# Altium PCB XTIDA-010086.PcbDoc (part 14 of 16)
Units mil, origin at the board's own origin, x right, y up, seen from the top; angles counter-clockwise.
Board outline 14763.78 x 8267.72 mil, 6 copper layers (Top Layer, GND Layer, Signal Layer 1, Signal Layer 2, Power Layer, Bottom Layer), stack 62 mil thick; 1933 components, 1002 nets, 4886 pads, 6482 vias.
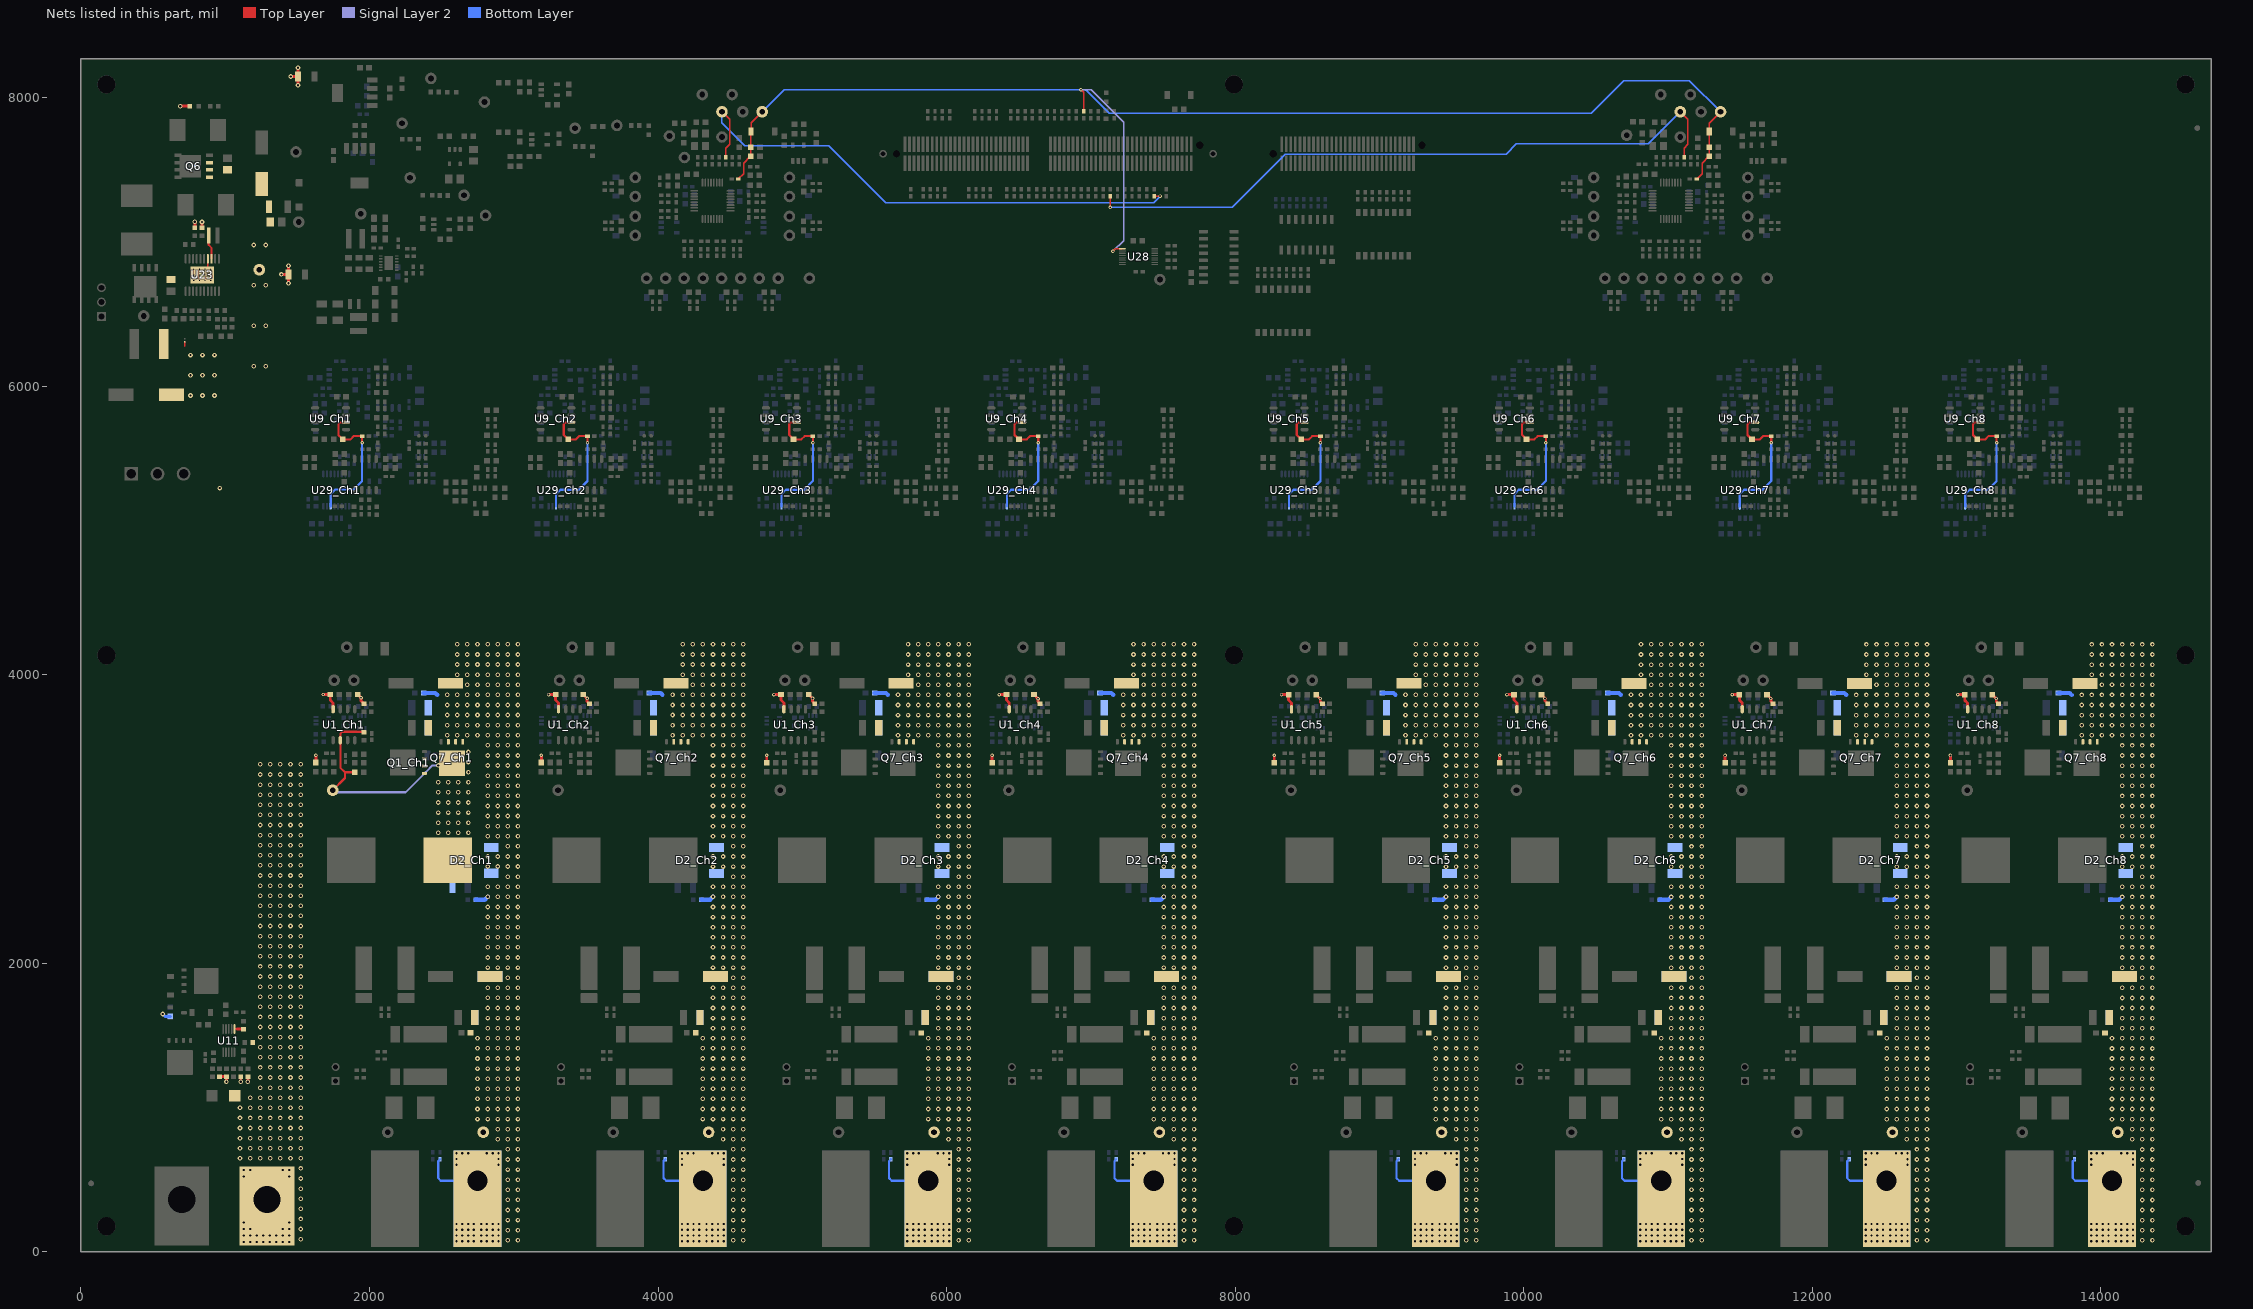
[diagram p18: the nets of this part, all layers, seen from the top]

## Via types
v1: diameter 32, hole 16, Top Layer to Bottom Layer, tented both sides, 4685 vias
v2: diameter 24, hole 12, Top Layer to Bottom Layer, tented both sides, 1013 vias
v3: diameter 32, hole 16, Top Layer to Bottom Layer, 728 vias
v4: diameter 19.68, hole 7.87, Top Layer to Bottom Layer, 40 vias
v5: diameter 214.57, hole 140, Top Layer to Bottom Layer, 16 vias

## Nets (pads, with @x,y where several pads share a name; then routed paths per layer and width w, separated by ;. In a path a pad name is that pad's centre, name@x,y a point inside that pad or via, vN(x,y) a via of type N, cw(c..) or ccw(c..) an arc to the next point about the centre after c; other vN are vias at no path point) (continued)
PGND: C3_Ch1.2 C3_Ch2.2 C3_Ch3.2 C3_Ch4.2 C3_Ch5.2 C3_Ch6.2 C3_Ch7.2 C3_Ch8.2 C4_Ch1.2 C4_Ch2.2 C4_Ch3.2 C4_Ch4.2 C4_Ch5.2 C4_Ch6.2 C4_Ch7.2 C4_Ch8.2 C5_Ch1.2 C5_Ch2.2 C5_Ch3.2 C5_Ch4.2 C5_Ch5.2 C5_Ch6.2 C5_Ch7.2 C5_Ch8.2 C6_Ch1.2 C6_Ch2.2 C6_Ch3.2 C6_Ch4.2 C6_Ch5.2 C6_Ch6.2 C6_Ch7.2 C6_Ch8.2 C7_Ch1.2 C7_Ch2.2 C7_Ch3.2 C7_Ch4.2 C7_Ch5.2 C7_Ch6.2 C7_Ch7.2 C7_Ch8.2 C8_Ch1.1 C8_Ch2.1 C8_Ch3.1 C8_Ch4.1 C8_Ch5.1 C8_Ch6.1 C8_Ch7.1 C8_Ch8.1 C9_Ch1.2 C9_Ch2.2 C9_Ch3.2 C9_Ch4.2 C9_Ch5.2 C9_Ch6.2 C9_Ch7.2 C9_Ch8.2 C10_Ch1.2 C10_Ch2.2 C10_Ch3.2 C10_Ch4.2 C10_Ch5.2 C10_Ch6.2 C10_Ch7.2 C10_Ch8.2 C11_Ch1.2 C11_Ch2.2 C11_Ch3.2 C11_Ch4.2 C11_Ch5.2 C11_Ch6.2 C11_Ch7.2 C11_Ch8.2 C12_Ch1.2 C12_Ch2.2 C12_Ch3.2 C12_Ch4.2 C12_Ch5.2 C12_Ch6.2 C12_Ch7.2 C12_Ch8.2 C13_Ch1.2 C13_Ch2.2 C13_Ch3.2 C13_Ch4.2 C13_Ch5.2 C13_Ch6.2 C13_Ch7.2 C13_Ch8.2 C15_Ch1.1 C15_Ch2.1 C15_Ch3.1 C15_Ch4.1 C15_Ch5.1 C15_Ch6.1 C15_Ch7.1 C15_Ch8.1 C56.1 C57.1 C58.2 C59.1 C109.2 C110.2 C111.2 C113.2 C114.2 C118.2 C119.2 C121.2 C137.2 D2_Ch1.1 D2_Ch1.3 D2_Ch2.1 D2_Ch2.3 D2_Ch3.1 D2_Ch3.3 D2_Ch4.1 D2_Ch4.3 D2_Ch5.1 D2_Ch5.3 D2_Ch6.1 D2_Ch6.3 D2_Ch7.1 D2_Ch7.3 D2_Ch8.1 D2_Ch8.3 D8.2 D11.1 J3_Ch1.1 J3_Ch2.1 J3_Ch3.1 J3_Ch4.1 J3_Ch5.1 J3_Ch6.1 J3_Ch7.1 J3_Ch8.1 NT1.2 Q6.1 Q6.2 Q6.3 Q7_Ch1.1 Q7_Ch1.2 Q7_Ch1.3 Q7_Ch2.1 Q7_Ch2.2 Q7_Ch2.3 Q7_Ch3.1 Q7_Ch3.2 Q7_Ch3.3 Q7_Ch4.1 Q7_Ch4.2 Q7_Ch4.3 Q7_Ch5.1 Q7_Ch5.2 Q7_Ch5.3 Q7_Ch6.1 Q7_Ch6.2 Q7_Ch6.3 Q7_Ch7.1 Q7_Ch7.2 Q7_Ch7.3 Q7_Ch8.1 Q7_Ch8.2 Q7_Ch8.3 R1_Ch1.2 R1_Ch2.2 R1_Ch3.2 R1_Ch4.2 R1_Ch5.2 R1_Ch6.2 R1_Ch7.2 R1_Ch8.2 R5_Ch1.1 R5_Ch2.1 R5_Ch3.1 R5_Ch4.1 R5_Ch5.1 R5_Ch6.1 R5_Ch7.1 R5_Ch8.1 R20_Ch1.1 R20_Ch2.1 R20_Ch3.1 R20_Ch4.1 R20_Ch5.1 R20_Ch6.1 R20_Ch7.1 R20_Ch8.1 R24_Ch1.1 R24_Ch2.1 R24_Ch3.1 R24_Ch4.1 R24_Ch5.1 R24_Ch6.1 R24_Ch7.1 R24_Ch8.1 R81.1 R88.1 R89.1 R152.1 R153.2 R211.1 T2.1 TP6_Ch1.1 TP6_Ch2.1 TP6_Ch3.1 TP6_Ch4.1 TP6_Ch5.1 TP6_Ch6.1 TP6_Ch7.1 TP6_Ch8.1 TP34.1 U1_Ch1.4 U1_Ch2.4 U1_Ch3.4 U1_Ch4.4 U1_Ch5.4 U1_Ch6.4 U1_Ch7.4 U1_Ch8.4 U11.6 U23.13 U23.14 U23.21 | length 8236.9
  Top Layer w10: U11.6@1064.7,1544.48 1083.48,1544.48
  Top Layer w12: 721,6277.7 NT1.2@721,6306.7 ; U23.21@841.5,6769.7 879.89,6808.09 U23.14@879.89,6881.91 ; R211.1@885.49,7043.7 885.49,6978.21 905.48,6958.22 U23.13@905.48,6881.91
  Top Layer w20: v1(689,7939.7) D11.1@754.5,7939.7 ; C118.2@789.5,7098.26 790,7098.76 v1(790,7137.7) ; C119.2@839.01,7097.76 C119.2@839.5,7098.26 v1(839.5,7137.2) ; R89.1@960.54,1214.2 C57.1@1009.04,1214.2 v1(1009.04,1178) ; 1083.48,1544.48 1126.85,1544.48 C56.1@1127.33,1544 C56.1@1127,1543.67 ; v1(1107.83,1177.8) R88.1@1107.83,1214 ; v1(1157.33,1177.8) C59.1@1157.33,1214 ; v1(1390,6773.7) R153.2@1439.11,6773.7 ; v1(1439.11,6712.81) R153.2@1439.11,6773.7 ; v1(1439.11,6834.59) R153.2@1439.11,6773.7 ; v1(1455.7,8145) R152.1@1504.81,8145 ; v1(1504.81,8084.11) R152.1@1504.81,8145 ; v1(1504.81,8205.89) R152.1@1504.81,8145 ; R24_Ch1.1@1629.36,3390.59 v2(1629.36,3440.86) ; v2(1679.31,3862.31) R5_Ch1.1@1728.62,3862.31 1728.62,3823.61 1748.37,3803.86 U1_Ch1.4@1748.37,3760.35 ; R1_Ch1.2@1919.61,3862.31 v2(1941.81,3840.11) 1941.81,3819.34 C8_Ch1.1@1962.33,3798.82 ; R24_Ch2.1@3191.36,3390.51 v2(3191.36,3440.79) ; v2(3241.31,3862.24) R5_Ch2.1@3290.62,3862.24 3290.62,3823.53 3310.37,3803.78 U1_Ch2.4@3310.37,3760.27 ; R1_Ch2.2@3481.61,3862.24 v2(3508.81,3835.04) 3508.81,3814.26 C8_Ch2.1@3524.33,3798.74 ; R24_Ch3.1@4753.36,3390.43 v2(4753.36,3440.71) ; v2(4803.31,3862.16) R5_Ch3.1@4852.62,3862.16 4852.62,3823.45 4872.37,3803.7 U1_Ch3.4@4872.37,3760.19 ; R1_Ch3.2@5043.61,3862.16 v2(5070.81,3834.96) 5070.81,3814.18 C8_Ch3.1@5086.33,3798.66 ; R24_Ch4.1@6315.36,3390.35 v2(6315.36,3440.63) ; v2(6365.31,3862.08) R5_Ch4.1@6414.62,3862.08 6414.62,3823.37 6434.37,3803.62 U1_Ch4.4@6434.37,3760.12 ; R1_Ch4.2@6605.61,3862.08 v2(6634.15,3833.53) 6634.15,3812.76 C8_Ch4.1@6648.33,3798.58 ; R24_Ch5.1@8271.06,3390.27 v2(8271.06,3440.55) ; v2(8321.01,3862) R5_Ch5.1@8370.32,3862 8370.32,3823.3 8390.07,3803.54 U1_Ch5.4@8390.07,3760.04 ; R1_Ch5.2@8561.31,3862 8588.51,3834.8 v2(8589.8,3834.8) 8589.8,3812.74 C8_Ch5.1@8604.03,3798.5 ; R24_Ch6.1@9833.06,3390.19 v2(9833.06,3440.47) ; v2(9883.01,3861.92) R5_Ch6.1@9932.32,3861.92 9932.32,3823.22 9952.07,3803.46 U1_Ch6.4@9952.07,3759.96 ; R1_Ch6.2@10123.31,3861.92 10146.7,3838.53 v2(10146.7,3834.72) 10146.7,3817.75 C8_Ch6.1@10166.03,3798.42 ; R24_Ch7.1@11395.06,3390.12 v2(11395.06,3440.39) ; v2(11445.01,3861.84) R5_Ch7.1@11494.32,3861.84 11494.32,3823.14 11514.07,3803.38 U1_Ch7.4@11514.07,3759.88 ; R1_Ch7.2@11685.31,3861.84 v2(11712.51,3834.64) 11712.51,3813.87 C8_Ch7.1@11728.03,3798.34 ; R24_Ch8.1@12957.06,3390.04 v2(12957.06,3440.31) ; v2(13007.01,3861.76) R5_Ch8.1@13056.32,3861.76 13056.32,3823.06 13076.07,3803.31 U1_Ch8.4@13076.07,3759.8 ; R1_Ch8.2@13247.31,3861.76 v2(13274.51,3834.56) 13274.51,3813.79 C8_Ch8.1@13290.03,3798.27
  Bottom Layer w15: R20_Ch1.1@2489,641.38 2476.5,628.88 2476.5,511.24 2494.74,493 v5(2749,493) ; R20_Ch2.1@4051,641.3 4038.5,628.8 4038.5,511.16 4056.74,492.92 v5(4311,492.92) ; R20_Ch3.1@5613,641.22 5600.5,628.72 5600.5,511.08 5618.74,492.84 v5(5873,492.84) ; R20_Ch4.1@7175,641.14 7162.5,628.64 7162.5,511 7180.74,492.76 v5(7435,492.76) ; R20_Ch5.1@9130.7,641.06 9118.2,628.56 9118.2,510.93 9136.44,492.69 v5(9390.7,492.69) ; R20_Ch6.1@10692.7,640.98 10680.2,628.48 10680.2,510.85 10698.44,492.61 v5(10952.7,492.61) ; R20_Ch7.1@12254.7,640.91 12242.2,628.41 12242.2,510.77 12260.44,492.53 v5(12514.7,492.53) ; R20_Ch8.1@13816.7,640.83 13804.2,628.33 13804.2,510.69 13822.44,492.45 v5(14076.7,492.45)
  Bottom Layer w20: v1(568,1648) 584.03,1631.97 R81.1@620.09,1631.97
  Bottom Layer w30: C7_Ch1.2@2377.5,3873 2456,3873 2469,3860 ; C15_Ch1.1@2737.56,2440 2799,2440 v1(2819,2460) ; C7_Ch2.2@3939.5,3872.92 4018,3872.92 4031,3859.92 ; C15_Ch2.1@4299.56,2439.92 4361,2439.92 v1(4381,2459.92) ; C7_Ch3.2@5501.5,3872.84 5580,3872.84 5593,3859.84 ; C15_Ch3.1@5861.56,2439.84 5923,2439.84 v1(5943,2459.84) ; C7_Ch4.2@7063.5,3872.76 7142,3872.76 7155,3859.76 ; C15_Ch4.1@7423.56,2439.76 7485,2439.76 v1(7505,2459.76) ; C7_Ch5.2@9019.2,3872.69 9097.7,3872.69 9110.7,3859.69 ; C15_Ch5.1@9379.26,2439.69 9440.7,2439.69 v1(9460.7,2459.69) ; C7_Ch6.2@10581.2,3872.61 10659.7,3872.61 10672.7,3859.61 ; C15_Ch6.1@10941.26,2439.61 11002.7,2439.61 v1(11022.7,2459.61) ; C7_Ch7.2@12143.2,3872.53 12221.7,3872.53 12234.7,3859.53 ; C15_Ch7.1@12503.26,2439.53 12564.7,2439.53 v1(12584.7,2459.53) ; C7_Ch8.2@13705.2,3872.45 13783.7,3872.45 13796.7,3859.45 ; C15_Ch8.1@14065.26,2439.45 14126.7,2439.45 v1(14146.7,2459.45)
  other v1: 11162.7,79.61 11232.7,79.61 12724.7,79.53 12794.7,79.53 14286.7,79.45 14356.7,79.45 2959,80 3029,80 4521,79.92 4591,79.92 6083,79.84 6153,79.84 7645,79.76 7715,79.76 9600.7,79.69 9670.7,79.69 1523,88 11162.7,149.61 11232.7,149.61 12724.7,149.53 12794.7,149.53 14286.7,149.45 14356.7,149.45 2959,150 3029,150 4521,149.92 4591,149.92 6083,149.84 6153,149.84 7645,149.76 7715,149.76 9600.7,149.69 9670.7,149.69 1523,158 11162.7,219.61 11232.7,219.61 12724.7,219.53 12794.7,219.53 14286.7,219.45 14356.7,219.45 2959,220 3029,220 4521,219.92 4591,219.92 6083,219.84 6153,219.84 7645,219.76 7715,219.76 9600.7,219.69 9670.7,219.69 1523,228 11162.7,289.61 11232.7,289.61 12724.7,289.53 12794.7,289.53 14286.7,289.45 14356.7,289.45 2959,290 3029,290 4521,289.92 4591,289.92 6083,289.84 6153,289.84 7645,289.76 7715,289.76 9600.7,289.69 9670.7,289.69 1523,298 11162.7,359.61 11232.7,359.61 12724.7,359.53 12794.7,359.53 14286.7,359.45 14356.7,359.45 2959,360 3029,360 4521,359.92 4591,359.92 6083,359.84 6153,359.84 7645,359.76 7715,359.76 9600.7,359.69 9670.7,359.69 1523,368 11162.7,429.61 11232.7,429.61 12724.7,429.53 12794.7,429.53 14286.7,429.45 14356.7,429.45 2959,430 3029,430 4521,429.92 4591,429.92 6083,429.84 6153,429.84 7645,429.76 7715,429.76 9600.7,429.69 9670.7,429.69 1523,438 11162.7,499.61 11232.7,499.61 12724.7,499.53 12794.7,499.53 14286.7,499.45 14356.7,499.45 2959,500 3029,500 4521,499.92 4591,499.92 6083,499.84 6153,499.84 7645,499.76 7715,499.76 9600.7,499.69 9670.7,499.69 1523,508 11162.7,569.61 11232.7,569.61 12724.7,569.53 12794.7,569.53 14286.7,569.45 14356.7,569.45 2959,570 3029,570 4521,569.92 4591,569.92 6083,569.84 6153,569.84 7645,569.76 7715,569.76 9600.7,569.69 9670.7,569.69 1523,578 11162.7,639.61 11232.7,639.61 12724.7,639.53 12794.7,639.53 14286.7,639.45 14356.7,639.45 2959,640 3029,640 4521,639.92 4591,639.92 6083,639.84 6153,639.84 7645,639.76 7715,639.76 9600.7,639.69 9670.7,639.69 1103,648 1173,648 1243,648 1313,648 1383,648 1453,648 1523,648 11162.7,709.61 11232.7,709.61 12724.7,709.53 12794.7,709.53 14286.7,709.45 14356.7,709.45 2959,710 3029,710 4521,709.92 4591,709.92 6083,709.84 6153,709.84 7645,709.76 7715,709.76 9600.7,709.69 9670.7,709.69 1103,718 1173,718 1243,718 1313,718 1383,718 1453,718 1523,718 11092.7,779.61 11162.7,779.61 11232.7,779.61 12654.7,779.53 12724.7,779.53 12794.7,779.53 14216.7,779.45 14286.7,779.45 14356.7,779.45 2889,780 2959,780 3029,780 4451,779.92 4521,779.92 4591,779.92 6013,779.84 6083,779.84 6153,779.84 7575,779.76 7645,779.76 7715,779.76 9530.7,779.69 9600.7,779.69 9670.7,779.69 1103,788 1173,788 1243,788 1313,788 1383,788 1453,788 1523,788 11092.7,849.61 11162.7,849.61 11232.7,849.61 12654.7,849.53 12724.7,849.53 12794.7,849.53 14216.7,849.45 14286.7,849.45 14356.7,849.45 2889,850 2959,850 3029,850 4451,849.92 4521,849.92 4591,849.92 6013,849.84 6083,849.84 6153,849.84 7575,849.76 7645,849.76 7715,849.76 9530.7,849.69 9600.7,849.69 9670.7,849.69 1103,858 1173,858 1243,858 1313,858 1383,858 1453,858 1523,858 10952.7,919.61 11022.7,919.61 11092.7,919.61 11162.7,919.61 11232.7,919.61 12514.7,919.53 12584.7,919.53 12654.7,919.53 12724.7,919.53 12794.7,919.53 14076.7,919.45 14146.7,919.45 14216.7,919.45 14286.7,919.45 14356.7,919.45 2749,920 2819,920 2889,920 2959,920 3029,920 4311,919.92 4381,919.92 4451,919.92 4521,919.92 4591,919.92 5873,919.84 5943,919.84 6013,919.84 6083,919.84 6153,919.84 7435,919.76 7505,919.76 7575,919.76 7645,919.76 7715,919.76 9390.7,919.69 9460.7,919.69 9530.7,919.69 9600.7,919.69 9670.7,919.69 1103,928 1173,928 1243,928 1313,928 1383,928 1453,928 1523,928 10952.7,989.61 11022.7,989.61 11092.7,989.61 11162.7,989.61 11232.7,989.61 12514.7,989.53 12584.7,989.53 12654.7,989.53 12724.7,989.53 12794.7,989.53 14076.7,989.45 14146.7,989.45 14216.7,989.45 14286.7,989.45 14356.7,989.45 2749,990 2819,990 2889,990 2959,990 3029,990 4311,989.92 4381,989.92 4451,989.92 4521,989.92 4591,989.92 5873,989.84 5943,989.84 6013,989.84 6083,989.84 6153,989.84 7435,989.76 7505,989.76 7575,989.76 7645,989.76 7715,989.76 9390.7,989.69 9460.7,989.69 9530.7,989.69 9600.7,989.69 9670.7,989.69 1103,998 1173,998 1243,998 1313,998 1383,998 1453,998 1523,998 10952.7,1059.61 11022.7,1059.61 11092.7,1059.61 11162.7,1059.61 11232.7,1059.61 12514.7,1059.53 12584.7,1059.53 12654.7,1059.53 12724.7,1059.53 12794.7,1059.53 14076.7,1059.45 14146.7,1059.45 14216.7,1059.45 14286.7,1059.45 14356.7,1059.45 2749,1060 2819,1060 2889,1060 2959,1060 3029,1060 4311,1059.92 4381,1059.92 4451,1059.92 4521,1059.92 4591,1059.92 5873,1059.84 5943,1059.84 6013,1059.84 6083,1059.84 6153,1059.84 7435,1059.76 7505,1059.76 7575,1059.76 7645,1059.76 7715,1059.76 9390.7,1059.69 9460.7,1059.69 9530.7,1059.69 9600.7,1059.69 9670.7,1059.69 1173,1068 1243,1068 1313,1068 1383,1068 1453,1068 1523,1068 10952.7,1129.61 11022.7,1129.61 11092.7,1129.61 11162.7,1129.61 11232.7,1129.61 12514.7,1129.53 12584.7,1129.53 12654.7,1129.53 12724.7,1129.53 12794.7,1129.53 14076.7,1129.45 14146.7,1129.45 14216.7,1129.45 14286.7,1129.45 14356.7,1129.45 2749,1130 2819,1130 2889,1130 2959,1130 3029,1130 4311,1129.92 4381,1129.92 4451,1129.92 4521,1129.92 4591,1129.92 5873,1129.84 5943,1129.84 6013,1129.84 6083,1129.84 6153,1129.84 7435,1129.76 7505,1129.76 7575,1129.76 7645,1129.76 7715,1129.76 9390.7,1129.69 9460.7,1129.69 9530.7,1129.69 9600.7,1129.69 9670.7,1129.69 1243,1138 1313,1138 1383,1138 1453,1138 1523,1138 10952.7,1199.61 11022.7,1199.61 11092.7,1199.61 11162.7,1199.61 11232.7,1199.61 12514.7,1199.53 12584.7,1199.53 12654.7,1199.53 12724.7,1199.53 12794.7,1199.53 14076.7,1199.45 14146.7,1199.45 14216.7,1199.45 14286.7,1199.45 14356.7,1199.45 2749,1200 2819,1200 2889,1200 2959,1200 3029,1200 4311,1199.92 4381,1199.92 4451,1199.92 4521,1199.92 4591,1199.92 5873,1199.84 5943,1199.84 6013,1199.84 6083,1199.84 6153,1199.84 7435,1199.76 7505,1199.76 7575,1199.76 7645,1199.76 7715,1199.76 9390.7,1199.69 9460.7,1199.69 9530.7,1199.69 9600.7,1199.69 9670.7,1199.69 1243,1208 1313,1208 1383,1208 1453,1208 1523,1208 10952.7,1269.61 11022.7,1269.61 11092.7,1269.61 11162.7,1269.61 11232.7,1269.61 12514.7,1269.53 12584.7,1269.53 12654.7,1269.53 12724.7,1269.53 12794.7,1269.53 14076.7,1269.45 14146.7,1269.45 14216.7,1269.45 14286.7,1269.45 14356.7,1269.45 2749,1270 2819,1270 2889,1270 2959,1270 3029,1270 4311,1269.92 4381,1269.92 4451,1269.92 4521,1269.92 4591,1269.92 5873,1269.84 5943,1269.84 6013,1269.84 6083,1269.84 6153,1269.84 7435,1269.76 7505,1269.76 7575,1269.76 7645,1269.76 7715,1269.76 9390.7,1269.69 9460.7,1269.69 9530.7,1269.69 9600.7,1269.69 9670.7,1269.69 1243,1278 1313,1278 1383,1278 1453,1278 1523,1278 10952.7,1339.61 11022.7,1339.61 11092.7,1339.61 11162.7,1339.61 11232.7,1339.61 12514.7,1339.53 12584.7,1339.53 12654.7,1339.53 12724.7,1339.53 12794.7,1339.53 14076.7,1339.45 14146.7,1339.45 14216.7,1339.45 14286.7,1339.45 14356.7,1339.45 2749,1340 2819,1340 2889,1340 2959,1340 3029,1340 4311,1339.92 4381,1339.92 4451,1339.92 4521,1339.92 4591,1339.92 5873,1339.84 5943,1339.84 6013,1339.84 6083,1339.84 6153,1339.84 7435,1339.76 7505,1339.76 7575,1339.76 7645,1339.76 7715,1339.76 9390.7,1339.69 9460.7,1339.69 9530.7,1339.69 9600.7,1339.69 9670.7,1339.69 1243,1348 1313,1348 1383,1348 1453,1348 1523,1348 10952.7,1409.61 11022.7,1409.61 11092.7,1409.61 11162.7,1409.61 11232.7,1409.61 12514.7,1409.53 12584.7,1409.53 12654.7,1409.53 12724.7,1409.53 12794.7,1409.53 14076.7,1409.45 14146.7,1409.45 14216.7,1409.45 14286.7,1409.45 14356.7,1409.45 2749,1410 2819,1410 2889,1410 2959,1410 3029,1410 4311,1409.92 4381,1409.92 4451,1409.92 4521,1409.92 4591,1409.92 5873,1409.84 5943,1409.84 6013,1409.84 6083,1409.84 6153,1409.84 7435,1409.76 7505,1409.76 7575,1409.76 7645,1409.76 7715,1409.76 9390.7,1409.69 9460.7,1409.69 9530.7,1409.69 9600.7,1409.69 9670.7,1409.69 1243,1418 1313,1418 1383,1418 1453,1418 1523,1418 10952.7,1479.61 11022.7,1479.61 11092.7,1479.61 11162.7,1479.61 11232.7,1479.61 12514.7,1479.53 12584.7,1479.53 12654.7,1479.53 12724.7,1479.53 12794.7,1479.53 14076.7,1479.45 14146.7,1479.45 14216.7,1479.45 14286.7,1479.45 14356.7,1479.45 2749,1480 2819,1480 2889,1480 2959,1480 3029,1480 4311,1479.92 4381,1479.92 4451,1479.92 4521,1479.92 4591,1479.92 5873,1479.84 5943,1479.84 6013,1479.84 6083,1479.84 6153,1479.84 7435,1479.76 7505,1479.76 7575,1479.76 7645,1479.76 7715,1479.76 9390.7,1479.69 9460.7,1479.69 9530.7,1479.69 9600.7,1479.69 9670.7,1479.69 1243,1488 1313,1488 1383,1488 1453,1488 1523,1488 11022.7,1549.61 11092.7,1549.61 11162.7,1549.61 11232.7,1549.61 12584.7,1549.53 12654.7,1549.53 12724.7,1549.53 12794.7,1549.53 14146.7,1549.45 14216.7,1549.45 14286.7,1549.45 14356.7,1549.45 2819,1550 2889,1550 2959,1550 3029,1550 4381,1549.92 4451,1549.92 4521,1549.92 4591,1549.92 5943,1549.84 6013,1549.84 6083,1549.84 6153,1549.84 7505,1549.76 7575,1549.76 7645,1549.76 7715,1549.76 9460.7,1549.69 9530.7,1549.69 9600.7,1549.69 9670.7,1549.69 1243,1558 1313,1558 1383,1558 1453,1558 1523,1558 11022.7,1619.61 11092.7,1619.61 11162.7,1619.61 11232.7,1619.61 12584.7,1619.53 12654.7,1619.53 12724.7,1619.53 12794.7,1619.53 14146.7,1619.45 14216.7,1619.45 14286.7,1619.45 14356.7,1619.45 2819,1620 2889,1620 2959,1620 3029,1620 4381,1619.92 4451,1619.92 4521,1619.92 4591,1619.92 5943,1619.84 6013,1619.84 6083,1619.84 6153,1619.84 7505,1619.76 7575,1619.76 7645,1619.76 7715,1619.76 9460.7,1619.69 9530.7,1619.69 9600.7,1619.69 9670.7,1619.69 1243,1628 1313,1628 1383,1628 1453,1628 1523,1628 11022.7,1689.61 11092.7,1689.61 11162.7,1689.61 11232.7,1689.61 12584.7,1689.53 12654.7,1689.53 12724.7,1689.53 12794.7,1689.53 14146.7,1689.45 14216.7,1689.45 14286.7,1689.45 14356.7,1689.45 2819,1690 2889,1690 2959,1690 3029,1690 4381,1689.92 4451,1689.92 4521,1689.92 4591,1689.92 5943,1689.84 6013,1689.84 6083,1689.84 6153,1689.84 7505,1689.76 7575,1689.76 7645,1689.76 7715,1689.76 9460.7,1689.69 9530.7,1689.69 9600.7,1689.69 9670.7,1689.69 1243,1698 1313,1698 1383,1698 1453,1698 1523,1698 11022.7,1759.61 11092.7,1759.61 11162.7,1759.61 11232.7,1759.61 12584.7,1759.53 12654.7,1759.53 12724.7,1759.53 12794.7,1759.53 14146.7,1759.45 14216.7,1759.45 14286.7,1759.45 14356.7,1759.45 2819,1760 2889,1760 2959,1760 3029,1760 4381,1759.92 4451,1759.92 4521,1759.92 4591,1759.92 5943,1759.84 6013,1759.84 6083,1759.84 6153,1759.84 7505,1759.76 7575,1759.76 7645,1759.76 7715,1759.76 9460.7,1759.69 9530.7,1759.69 9600.7,1759.69 9670.7,1759.69 1243,1768 1313,1768 1383,1768 1453,1768 1523,1768 11022.7,1829.61 11092.7,1829.61 11162.7,1829.61 11232.7,1829.61 12584.7,1829.53 12654.7,1829.53 12724.7,1829.53 12794.7,1829.53 14146.7,1829.45 14216.7,1829.45 14286.7,1829.45 14356.7,1829.45 2819,1830 2889,1830 2959,1830 3029,1830 4381,1829.92 4451,1829.92 4521,1829.92 4591,1829.92 5943,1829.84 6013,1829.84 6083,1829.84 6153,1829.84 7505,1829.76 7575,1829.76 7645,1829.76 7715,1829.76 9460.7,1829.69 9530.7,1829.69 9600.7,1829.69 9670.7,1829.69 1243,1838 1313,1838 1383,1838 1453,1838 1523,1838 11162.7,1899.61 11232.7,1899.61 12724.7,1899.53 12794.7,1899.53 14286.7,1899.45 14356.7,1899.45 2959,1900 3029,1900 4521,1899.92 4591,1899.92 6083,1899.84 6153,1899.84 7645,1899.76 7715,1899.76 9600.7,1899.69 9670.7,1899.69 1243,1908 1313,1908 1383,1908 1453,1908 1523,1908 11022.7,1969.61 11092.7,1969.61 11162.7,1969.61 11232.7,1969.61 12584.7,1969.53 12654.7,1969.53 12724.7,1969.53 12794.7,1969.53 14146.7,1969.45 14216.7,1969.45 14286.7,1969.45 14356.7,1969.45 2819,1970 2889,1970 2959,1970 3029,1970 4381,1969.92 4451,1969.92 4521,1969.92 4591,1969.92 5943,1969.84 6013,1969.84 6083,1969.84 6153,1969.84 7505,1969.76 7575,1969.76 7645,1969.76 7715,1969.76 9460.7,1969.69 9530.7,1969.69 9600.7,1969.69 9670.7,1969.69 1243,1978 1313,1978 1383,1978 1453,1978 1523,1978 11022.7,2039.61 11092.7,2039.61 11162.7,2039.61 11232.7,2039.61 12584.7,2039.53 12654.7,2039.53 12724.7,2039.53 12794.7,2039.53 14146.7,2039.45 14216.7,2039.45 14286.7,2039.45 14356.7,2039.45 2819,2040 2889,2040 2959,2040 3029,2040 4381,2039.92 4451,2039.92 4521,2039.92 4591,2039.92 5943,2039.84 6013,2039.84 6083,2039.84 6153,2039.84 7505,2039.76 7575,2039.76 7645,2039.76 7715,2039.76 9460.7,2039.69 9530.7,2039.69 9600.7,2039.69 9670.7,2039.69 1243,2048 1313,2048 1383,2048 1453,2048 1523,2048 11022.7,2109.61 11092.7,2109.61 11162.7,2109.61 11232.7,2109.61 12584.7,2109.53 12654.7,2109.53 12724.7,2109.53 12794.7,2109.53 14146.7,2109.45 14216.7,2109.45 14286.7,2109.45 14356.7,2109.45 2819,2110 2889,2110 2959,2110 3029,2110 4381,2109.92 4451,2109.92 4521,2109.92 4591,2109.92 5943,2109.84 6013,2109.84 6083,2109.84 6153,2109.84 7505,2109.76 7575,2109.76 7645,2109.76 7715,2109.76 9460.7,2109.69 9530.7,2109.69 9600.7,2109.69 9670.7,2109.69 1243,2118 1313,2118 1383,2118 1453,2118 1523,2118 11022.7,2179.61 11092.7,2179.61 11162.7,2179.61 11232.7,2179.61 12584.7,2179.53 12654.7,2179.53 12724.7,2179.53 12794.7,2179.53 14146.7,2179.45 14216.7,2179.45 14286.7,2179.45 14356.7,2179.45 2819,2180 2889,2180 2959,2180 3029,2180 4381,2179.92 4451,2179.92 4521,2179.92 4591,2179.92 5943,2179.84 6013,2179.84 6083,2179.84 6153,2179.84 7505,2179.76 7575,2179.76 7645,2179.76 7715,2179.76 9460.7,2179.69 9530.7,2179.69 9600.7,2179.69 9670.7,2179.69 1243,2188 1313,2188 1383,2188 1453,2188 1523,2188 11022.7,2249.61 11092.7,2249.61 11162.7,2249.61 11232.7,2249.61 12584.7,2249.53 12654.7,2249.53 12724.7,2249.53 12794.7,2249.53 14146.7,2249.45 14216.7,2249.45 14286.7,2249.45 14356.7,2249.45 2819,2250 2889,2250 2959,2250 3029,2250 4381,2249.92 4451,2249.92 4521,2249.92 4591,2249.92 5943,2249.84 6013,2249.84 6083,2249.84 6153,2249.84 7505,2249.76 7575,2249.76 7645,2249.76 7715,2249.76 9460.7,2249.69 9530.7,2249.69 9600.7,2249.69 9670.7,2249.69 1243,2258 1313,2258 1383,2258 1453,2258 1523,2258 11022.7,2319.61 11092.7,2319.61 11162.7,2319.61 11232.7,2319.61 12584.7,2319.53 12654.7,2319.53 12724.7,2319.53 12794.7,2319.53 14146.7,2319.45 14216.7,2319.45 14286.7,2319.45 14356.7,2319.45 2819,2320 2889,2320 2959,2320 3029,2320 4381,2319.92 4451,2319.92 4521,2319.92 4591,2319.92 5943,2319.84 6013,2319.84 6083,2319.84 6153,2319.84 7505,2319.76 7575,2319.76 7645,2319.76 7715,2319.76 9460.7,2319.69 9530.7,2319.69 9600.7,2319.69 9670.7,2319.69 1243,2328 1313,2328 1383,2328 1453,2328 1523,2328 11022.7,2389.61 11092.7,2389.61 11162.7,2389.61 11232.7,2389.61 12584.7,2389.53 12654.7,2389.53 12724.7,2389.53 12794.7,2389.53 14146.7,2389.45 14216.7,2389.45 14286.7,2389.45 14356.7,2389.45 2819,2390 2889,2390 2959,2390 3029,2390 4381,2389.92 4451,2389.92 4521,2389.92 4591,2389.92 5943,2389.84 6013,2389.84 6083,2389.84 6153,2389.84 7505,2389.76 7575,2389.76 7645,2389.76 7715,2389.76 9460.7,2389.69 9530.7,2389.69 9600.7,2389.69 9670.7,2389.69 1243,2398 1313,2398 1383,2398 1453,2398 1523,2398 11092.7,2459.61 11162.7,2459.61 11232.7,2459.61 12654.7,2459.53 12724.7,2459.53 12794.7,2459.53 14216.7,2459.45 14286.7,2459.45 14356.7,2459.45 2889,2460 2959,2460 3029,2460 4451,2459.92 4521,2459.92 4591,2459.92 6013,2459.84 6083,2459.84 6153,2459.84 7575,2459.76 7645,2459.76 7715,2459.76 9530.7,2459.69 9600.7,2459.69 9670.7,2459.69 1243,2468 1313,2468 1383,2468 1453,2468 1523,2468 11022.7,2529.61 11092.7,2529.61 11162.7,2529.61 11232.7,2529.61 12584.7,2529.53 12654.7,2529.53 12724.7,2529.53 12794.7,2529.53 14146.7,2529.45 14216.7,2529.45 14286.7,2529.45 14356.7,2529.45 2819,2530 2889,2530 2959,2530 3029,2530 4381,2529.92 4451,2529.92 4521,2529.92 4591,2529.92 5943,2529.84 6013,2529.84 6083,2529.84 6153,2529.84 7505,2529.76 7575,2529.76 7645,2529.76 7715,2529.76 9460.7,2529.69 9530.7,2529.69 9600.7,2529.69 9670.7,2529.69 1243,2538 1313,2538 1383,2538 1453,2538 1523,2538 11162.7,2599.61 11232.7,2599.61 12724.7,2599.53 12794.7,2599.53 14286.7,2599.45 14356.7,2599.45 2959,2600 3029,2600 4521,2599.92 4591,2599.92 6083,2599.84 6153,2599.84 7645,2599.76 7715,2599.76 9600.7,2599.69 9670.7,2599.69 1243,2608 1313,2608 1383,2608 1453,2608 1523,2608 11022.7,2669.61 11092.7,2669.61 11162.7,2669.61 11232.7,2669.61 12584.7,2669.53 12654.7,2669.53 12724.7,2669.53 12794.7,2669.53 14146.7,2669.45 14216.7,2669.45 14286.7,2669.45 14356.7,2669.45 2819,2670 2889,2670 2959,2670 3029,2670 4381,2669.92 4451,2669.92 4521,2669.92 4591,2669.92 5943,2669.84 6013,2669.84 6083,2669.84 6153,2669.84 7505,2669.76 7575,2669.76 7645,2669.76 7715,2669.76 9460.7,2669.69 9530.7,2669.69 9600.7,2669.69 9670.7,2669.69 1243,2678 1313,2678 1383,2678 1453,2678 1523,2678 11022.7,2739.61 11092.7,2739.61 11162.7,2739.61 11232.7,2739.61 12584.7,2739.53 12654.7,2739.53 12724.7,2739.53 12794.7,2739.53 14146.7,2739.45 14216.7,2739.45 14286.7,2739.45 14356.7,2739.45 2819,2740 2889,2740 2959,2740 3029,2740 4381,2739.92 4451,2739.92 4521,2739.92 4591,2739.92 5943,2739.84 6013,2739.84 6083,2739.84 6153,2739.84 7505,2739.76 7575,2739.76 7645,2739.76 7715,2739.76 9460.7,2739.69 9530.7,2739.69 9600.7,2739.69 9670.7,2739.69 1243,2748 1313,2748 1383,2748 1453,2748 1523,2748 11162.7,2809.61 11232.7,2809.61 12724.7,2809.53 12794.7,2809.53 14286.7,2809.45 14356.7,2809.45 2959,2810 3029,2810 4521,2809.92 4591,2809.92 6083,2809.84 6153,2809.84 7645,2809.76 7715,2809.76 9600.7,2809.69 9670.7,2809.69 1243,2818 1313,2818 1383,2818 1453,2818 1523,2818 11022.7,2879.61 11092.7,2879.61 11162.7,2879.61 11232.7,2879.61 12584.7,2879.53 12654.7,2879.53 12724.7,2879.53 12794.7,2879.53 14146.7,2879.45 14216.7,2879.45 14286.7,2879.45 14356.7,2879.45 2819,2880 2889,2880 2959,2880 3029,2880 4381,2879.92 4451,2879.92 4521,2879.92 4591,2879.92 5943,2879.84 6013,2879.84 6083,2879.84 6153,2879.84 7505,2879.76 7575,2879.76 7645,2879.76 7715,2879.76 9460.7,2879.69 9530.7,2879.69 9600.7,2879.69 9670.7,2879.69 1243,2888 1313,2888 1383,2888 1453,2888 1523,2888 11022.7,2949.61 11092.7,2949.61 11162.7,2949.61 11232.7,2949.61 12584.7,2949.53 12654.7,2949.53 12724.7,2949.53 12794.7,2949.53 14146.7,2949.45 14216.7,2949.45 14286.7,2949.45 14356.7,2949.45 2819,2950 2889,2950 2959,2950 3029,2950 4381,2949.92 4451,2949.92 4521,2949.92 4591,2949.92 5943,2949.84 6013,2949.84 6083,2949.84 6153,2949.84 7505,2949.76 7575,2949.76 7645,2949.76 7715,2949.76 9460.7,2949.69 9530.7,2949.69 9600.7,2949.69 9670.7,2949.69 1243,2958 1313,2958 1383,2958 1453,2958 1523,2958 11022.7,3019.61 11092.7,3019.61 11162.7,3019.61 11232.7,3019.61 12584.7,3019.53 12654.7,3019.53 12724.7,3019.53 12794.7,3019.53 14146.7,3019.45 14216.7,3019.45 14286.7,3019.45 14356.7,3019.45 2819,3020 2889,3020 2959,3020 3029,3020 4381,3019.92 4451,3019.92 4521,3019.92 4591,3019.92 5943,3019.84 6013,3019.84 6083,3019.84 6153,3019.84 7505,3019.76 7575,3019.76 7645,3019.76 7715,3019.76 9460.7,3019.69 9530.7,3019.69 9600.7,3019.69 9670.7,3019.69 1243,3028 1313,3028 1383,3028 1453,3028 1523,3028 11022.7,3089.61 11092.7,3089.61 11162.7,3089.61 11232.7,3089.61 12584.7,3089.53 12654.7,3089.53 12724.7,3089.53 12794.7,3089.53 14146.7,3089.45 14216.7,3089.45 14286.7,3089.45 14356.7,3089.45 2819,3090 2889,3090 2959,3090 3029,3090 4381,3089.92 4451,3089.92 4521,3089.92 4591,3089.92 5943,3089.84 6013,3089.84 6083,3089.84 6153,3089.84 7505,3089.76 7575,3089.76 7645,3089.76 7715,3089.76 9460.7,3089.69 9530.7,3089.69 9600.7,3089.69 9670.7,3089.69 1243,3098 1313,3098 1383,3098 1453,3098 1523,3098 11022.7,3159.61 11092.7,3159.61 11162.7,3159.61 11232.7,3159.61 12584.7,3159.53 12654.7,3159.53 12724.7,3159.53 12794.7,3159.53 14146.7,3159.45 14216.7,3159.45 14286.7,3159.45 14356.7,3159.45 2819,3160 2889,3160 2959,3160 3029,3160 4381,3159.92 4451,3159.92 4521,3159.92 4591,3159.92 5943,3159.84 6013,3159.84 6083,3159.84 6153,3159.84 7505,3159.76 7575,3159.76 7645,3159.76 7715,3159.76 9460.7,3159.69 9530.7,3159.69 9600.7,3159.69 9670.7,3159.69 1243,3168 1313,3168 1383,3168 1453,3168 1523,3168 11022.7,3229.61 11092.7,3229.61 11162.7,3229.61 11232.7,3229.61 12584.7,3229.53 12654.7,3229.53 12724.7,3229.53 12794.7,3229.53 14146.7,3229.45 14216.7,3229.45 14286.7,3229.45 14356.7,3229.45 2819,3230 2889,3230 2959,3230 3029,3230 4381,3229.92 4451,3229.92 4521,3229.92 4591,3229.92 5943,3229.84 6013,3229.84 6083,3229.84 6153,3229.84 7505,3229.76 7575,3229.76 7645,3229.76 7715,3229.76 9460.7,3229.69 9530.7,3229.69 9600.7,3229.69 9670.7,3229.69 1243,3238 1313,3238 1383,3238 1453,3238 1523,3238 11022.7,3299.61 11092.7,3299.61 11162.7,3299.61 11232.7,3299.61 12584.7,3299.53 12654.7,3299.53 12724.7,3299.53 12794.7,3299.53 14146.7,3299.45 14216.7,3299.45 14286.7,3299.45 14356.7,3299.45 2819,3300 2889,3300 2959,3300 3029,3300 4381,3299.92 4451,3299.92 4521,3299.92 4591,3299.92 5943,3299.84 6013,3299.84 6083,3299.84 6153,3299.84 7505,3299.76 7575,3299.76 7645,3299.76 7715,3299.76 9460.7,3299.69 9530.7,3299.69 9600.7,3299.69 9670.7,3299.69 1243,3308 1313,3308 1383,3308 1453,3308 1523,3308 11022.7,3369.61 11092.7,3369.61 11162.7,3369.61 11232.7,3369.61 12584.7,3369.53 12654.7,3369.53 12724.7,3369.53 12794.7,3369.53 14146.7,3369.45 14216.7,3369.45 14286.7,3369.45 14356.7,3369.45 2819,3370 2889,3370 2959,3370 3029,3370 4381,3369.92 4451,3369.92 4521,3369.92 4591,3369.92 5943,3369.84 6013,3369.84 6083,3369.84 6153,3369.84 7505,3369.76 7575,3369.76 7645,3369.76 7715,3369.76 9460.7,3369.69 9530.7,3369.69 9600.7,3369.69 9670.7,3369.69 1243,3378 1313,3378 1383,3378 1453,3378 1523,3378 11022.7,3439.61 11092.7,3439.61 11162.7,3439.61 11232.7,3439.61 12584.7,3439.53 12654.7,3439.53 12724.7,3439.53 12794.7,3439.53 14146.7,3439.45 14216.7,3439.45 14286.7,3439.45 14356.7,3439.45 2819,3440 2889,3440 2959,3440 3029,3440 4381,3439.92 4451,3439.92 4521,3439.92 4591,3439.92 5943,3439.84 6013,3439.84 6083,3439.84 6153,3439.84 7505,3439.76 7575,3439.76 7645,3439.76 7715,3439.76 9460.7,3439.69 9530.7,3439.69 9600.7,3439.69 9670.7,3439.69 11022.7,3509.61 11092.7,3509.61 11162.7,3509.61 11232.7,3509.61 12584.7,3509.53 12654.7,3509.53 12724.7,3509.53 12794.7,3509.53 14146.7,3509.45 14216.7,3509.45 14286.7,3509.45 14356.7,3509.45 2819,3510 2889,3510 2959,3510 3029,3510 4381,3509.92 4451,3509.92 4521,3509.92 4591,3509.92 5943,3509.84 6013,3509.84 6083,3509.84 6153,3509.84 7505,3509.76 7575,3509.76 7645,3509.76 7715,3509.76 9460.7,3509.69 9530.7,3509.69 9600.7,3509.69 9670.7,3509.69 10742.7,3579.61 10812.7,3579.61 10882.7,3579.61 10952.7,3579.61 11022.7,3579.61 11092.7,3579.61 11162.7,3579.61 11232.7,3579.61 12304.7,3579.53 12374.7,3579.53 12444.7,3579.53 12514.7,3579.53 12584.7,3579.53 12654.7,3579.53 12724.7,3579.53 12794.7,3579.53 13866.7,3579.45 13936.7,3579.45 14006.7,3579.45 14076.7,3579.45 14146.7,3579.45 14216.7,3579.45 14286.7,3579.45 14356.7,3579.45 2539,3580 2609,3580 2679,3580 2749,3580 2819,3580 2889,3580 2959,3580 3029,3580 4101,3579.92 4171,3579.92 4241,3579.92 4311,3579.92 4381,3579.92 4451,3579.92 4521,3579.92 4591,3579.92 5663,3579.84 5733,3579.84 5803,3579.84 5873,3579.84 5943,3579.84 6013,3579.84 6083,3579.84 6153,3579.84 7225,3579.76 7295,3579.76 7365,3579.76 7435,3579.76 7505,3579.76 7575,3579.76 7645,3579.76 7715,3579.76 9180.7,3579.69 9250.7,3579.69 9320.7,3579.69 9390.7,3579.69 9460.7,3579.69 9530.7,3579.69 9600.7,3579.69 9670.7,3579.69 10742.7,3649.61 10812.7,3649.61 10882.7,3649.61 10952.7,3649.61 11022.7,3649.61 11092.7,3649.61 11162.7,3649.61 11232.7,3649.61 12304.7,3649.53 12374.7,3649.53 12444.7,3649.53 12514.7,3649.53 12584.7,3649.53 12654.7,3649.53 12724.7,3649.53 12794.7,3649.53 13866.7,3649.45 13936.7,3649.45 14006.7,3649.45 14076.7,3649.45 14146.7,3649.45 14216.7,3649.45 14286.7,3649.45 14356.7,3649.45 2539,3650 2609,3650 2679,3650 2749,3650 2819,3650 2889,3650 2959,3650 3029,3650 4101,3649.92 4171,3649.92 4241,3649.92 4311,3649.92 4381,3649.92 4451,3649.92 4521,3649.92 4591,3649.92 5663,3649.84 5733,3649.84 5803,3649.84 5873,3649.84 5943,3649.84 6013,3649.84 6083,3649.84 6153,3649.84 7225,3649.76 7295,3649.76 7365,3649.76 7435,3649.76 7505,3649.76 7575,3649.76 7645,3649.76 7715,3649.76 9180.7,3649.69 9250.7,3649.69 9320.7,3649.69 9390.7,3649.69 9460.7,3649.69 9530.7,3649.69 9600.7,3649.69 9670.7,3649.69 10742.7,3719.61 10812.7,3719.61 10882.7,3719.61 10952.7,3719.61 11022.7,3719.61 11092.7,3719.61 11162.7,3719.61 11232.7,3719.61 12304.7,3719.53 12374.7,3719.53 12444.7,3719.53 12514.7,3719.53 12584.7,3719.53 12654.7,3719.53 12724.7,3719.53 12794.7,3719.53 13866.7,3719.45 13936.7,3719.45 14006.7,3719.45 14076.7,3719.45 14146.7,3719.45 14216.7,3719.45 14286.7,3719.45 14356.7,3719.45 2539,3720 2609,3720 2679,3720 2749,3720 2819,3720 2889,3720 2959,3720 3029,3720 4101,3719.92 4171,3719.92 4241,3719.92 4311,3719.92 4381,3719.92 4451,3719.92 4521,3719.92 4591,3719.92 5663,3719.84 5733,3719.84 5803,3719.84 5873,3719.84 5943,3719.84 6013,3719.84 6083,3719.84 6153,3719.84 7225,3719.76 7295,3719.76 7365,3719.76 7435,3719.76 7505,3719.76 7575,3719.76 7645,3719.76 7715,3719.76 9180.7,3719.69 9250.7,3719.69 9320.7,3719.69 9390.7,3719.69 9460.7,3719.69 9530.7,3719.69 9600.7,3719.69 9670.7,3719.69 10742.7,3789.61 10812.7,3789.61 10882.7,3789.61 10952.7,3789.61 11022.7,3789.61 11092.7,3789.61 11162.7,3789.61 11232.7,3789.61 12304.7,3789.53 12374.7,3789.53 12444.7,3789.53 12514.7,3789.53 12584.7,3789.53 12654.7,3789.53 12724.7,3789.53 12794.7,3789.53 13866.7,3789.45 13936.7,3789.45 14006.7,3789.45 14076.7,3789.45 14146.7,3789.45 14216.7,3789.45 14286.7,3789.45 14356.7,3789.45 2539,3790 2609,3790 2679,3790 2749,3790 2819,3790 2889,3790 2959,3790 3029,3790 4101,3789.92 4171,3789.92 4241,3789.92 4311,3789.92 4381,3789.92 4451,3789.92 4521,3789.92 4591,3789.92 5663,3789.84 5733,3789.84 5803,3789.84 5873,3789.84 5943,3789.84 6013,3789.84 6083,3789.84 6153,3789.84 7225,3789.76 7295,3789.76 7365,3789.76 7435,3789.76 7505,3789.76 7575,3789.76 7645,3789.76 7715,3789.76 9180.7,3789.69 9250.7,3789.69 9320.7,3789.69 9390.7,3789.69 9460.7,3789.69 9530.7,3789.69 9600.7,3789.69 9670.7,3789.69 10742.7,3859.61 10812.7,3859.61 10882.7,3859.61 10952.7,3859.61 11022.7,3859.61 11092.7,3859.61 11162.7,3859.61 11232.7,3859.61 12304.7,3859.53 12374.7,3859.53 12444.7,3859.53 12514.7,3859.53 12584.7,3859.53 12654.7,3859.53 12724.7,3859.53 12794.7,3859.53 13866.7,3859.45 13936.7,3859.45 14006.7,3859.45 14076.7,3859.45 14146.7,3859.45 14216.7,3859.45 14286.7,3859.45 14356.7,3859.45 2539,3860 2609,3860 2679,3860 2749,3860 2819,3860 2889,3860 2959,3860 3029,3860 4101,3859.92 4171,3859.92 4241,3859.92 4311,3859.92 4381,3859.92 4451,3859.92 4521,3859.92 4591,3859.92 5663,3859.84 5733,3859.84 5803,3859.84 5873,3859.84 5943,3859.84 6013,3859.84 6083,3859.84 6153,3859.84 7225,3859.76 7295,3859.76 7365,3859.76 7435,3859.76 7505,3859.76 7575,3859.76 7645,3859.76 7715,3859.76 9180.7,3859.69 9250.7,3859.69 9320.7,3859.69 9390.7,3859.69 9460.7,3859.69 9530.7,3859.69 9600.7,3859.69 9670.7,3859.69 10882.7,3929.61 10952.7,3929.61 11022.7,3929.61 11092.7,3929.61 11162.7,3929.61 11232.7,3929.61 12444.7,3929.53 12514.7,3929.53 12584.7,3929.53 12654.7,3929.53 12724.7,3929.53 12794.7,3929.53 14006.7,3929.45 14076.7,3929.45 14146.7,3929.45 14216.7,3929.45 14286.7,3929.45 14356.7,3929.45 2679,3930 2749,3930 2819,3930 2889,3930 2959,3930 3029,3930 4241,3929.92 4311,3929.92 4381,3929.92 4451,3929.92 4521,3929.92 4591,3929.92 5803,3929.84 5873,3929.84 5943,3929.84 6013,3929.84 6083,3929.84 6153,3929.84 7365,3929.76 7435,3929.76 7505,3929.76 7575,3929.76 7645,3929.76 7715,3929.76 9320.7,3929.69 9390.7,3929.69 9460.7,3929.69 9530.7,3929.69 9600.7,3929.69 9670.7,3929.69 10812.7,3999.61 10882.7,3999.61 10952.7,3999.61 11022.7,3999.61 11092.7,3999.61 11162.7,3999.61 11232.7,3999.61 12374.7,3999.53 12444.7,3999.53 12514.7,3999.53 12584.7,3999.53 12654.7,3999.53 12724.7,3999.53 12794.7,3999.53 13936.7,3999.45 14006.7,3999.45 14076.7,3999.45 14146.7,3999.45 14216.7,3999.45 14286.7,3999.45 14356.7,3999.45 2609,4000 2679,4000 2749,4000 2819,4000 2889,4000 2959,4000 3029,4000 4171,3999.92 4241,3999.92 4311,3999.92 4381,3999.92 4451,3999.92 4521,3999.92 4591,3999.92 5733,3999.84 5803,3999.84 5873,3999.84 5943,3999.84 6013,3999.84 6083,3999.84 6153,3999.84 7295,3999.76 7365,3999.76 7435,3999.76 7505,3999.76 7575,3999.76 7645,3999.76 7715,3999.76 9250.7,3999.69 9320.7,3999.69 9390.7,3999.69 9460.7,3999.69 9530.7,3999.69 9600.7,3999.69 9670.7,3999.69 10812.7,4069.61 10882.7,4069.61 10952.7,4069.61 11022.7,4069.61 11092.7,4069.61 11162.7,4069.61 11232.7,4069.61 12374.7,4069.53 12444.7,4069.53 12514.7,4069.53 12584.7,4069.53 12654.7,4069.53 12724.7,4069.53 12794.7,4069.53 13936.7,4069.45 14006.7,4069.45 14076.7,4069.45 14146.7,4069.45 14216.7,4069.45 14286.7,4069.45 14356.7,4069.45 2609,4070 2679,4070 2749,4070 2819,4070 2889,4070 2959,4070 3029,4070 4171,4069.92 4241,4069.92 4311,4069.92 4381,4069.92 4451,4069.92 4521,4069.92 4591,4069.92 5733,4069.84 5803,4069.84 5873,4069.84 5943,4069.84 6013,4069.84 6083,4069.84 6153,4069.84 7295,4069.76 7365,4069.76 7435,4069.76 7505,4069.76 7575,4069.76 7645,4069.76 7715,4069.76 9250.7,4069.69 9320.7,4069.69 9390.7,4069.69 9460.7,4069.69 9530.7,4069.69 9600.7,4069.69 9670.7,4069.69 10812.7,4139.61 10882.7,4139.61 10952.7,4139.61 11022.7,4139.61 11092.7,4139.61 11162.7,4139.61 11232.7,4139.61 12374.7,4139.53 12444.7,4139.53 12514.7,4139.53 12584.7,4139.53 12654.7,4139.53 12724.7,4139.53 12794.7,4139.53 13936.7,4139.45 14006.7,4139.45 14076.7,4139.45 14146.7,4139.45 14216.7,4139.45 14286.7,4139.45 14356.7,4139.45 2609,4140 2679,4140 2749,4140 2819,4140 2889,4140 2959,4140 3029,4140 4171,4139.92 4241,4139.92 4311,4139.92 4381,4139.92 4451,4139.92 4521,4139.92 4591,4139.92 5733,4139.84 5803,4139.84 5873,4139.84 5943,4139.84 6013,4139.84 6083,4139.84 6153,4139.84 7295,4139.76 7365,4139.76 7435,4139.76 7505,4139.76 7575,4139.76 7645,4139.76 7715,4139.76 9250.7,4139.69 9320.7,4139.69 9390.7,4139.69 9460.7,4139.69 9530.7,4139.69 9600.7,4139.69 9670.7,4139.69 10812.7,4209.61 10882.7,4209.61 10952.7,4209.61 11022.7,4209.61 11092.7,4209.61 11162.7,4209.61 11232.7,4209.61 12374.7,4209.53 12444.7,4209.53 12514.7,4209.53 12584.7,4209.53 12654.7,4209.53 12724.7,4209.53 12794.7,4209.53 13936.7,4209.45 14006.7,4209.45 14076.7,4209.45 14146.7,4209.45 14216.7,4209.45 14286.7,4209.45 14356.7,4209.45 2609,4210 2679,4210 2749,4210 2819,4210 2889,4210 2959,4210 3029,4210 4171,4209.92 4241,4209.92 4311,4209.92 4381,4209.92 4451,4209.92 4521,4209.92 4591,4209.92 5733,4209.84 5803,4209.84 5873,4209.84 5943,4209.84 6013,4209.84 6083,4209.84 6153,4209.84 7295,4209.76 7365,4209.76 7435,4209.76 7505,4209.76 7575,4209.76 7645,4209.76 7715,4209.76 9250.7,4209.69 9320.7,4209.69 9390.7,4209.69 9460.7,4209.69 9530.7,4209.69 9600.7,4209.69 9670.7,4209.69 963,5293 760,5934.7 843,5934.7 926,5934.7 760,6074.7 843,6074.7 926,6074.7 1198,6137.7 1281,6137.7 760,6214.7 843,6214.7 926,6214.7 1198,6417.7 1281,6417.7 1198,6697.7 1281,6697.7 1198,6977.7 1281,6977.7
  other v3: 1129.33,67.56 1174.33,67.56 1219.33,67.56 1264.33,67.56 1309.33,67.56 1354.33,67.56 1399.33,67.56 1444.33,67.56 10807.7,72.61 10847.7,72.61 10887.7,72.61 10927.7,72.61 10977.7,72.61 11017.7,72.61 11057.7,72.61 11097.7,72.61 12369.7,72.53 12409.7,72.53 12449.7,72.53 12489.7,72.53 12539.7,72.53 12579.7,72.53 12619.7,72.53 12659.7,72.53 13931.7,72.45 13971.7,72.45 14011.7,72.45 14051.7,72.45 14101.7,72.45 14141.7,72.45 14181.7,72.45 14221.7,72.45 2604,73 2644,73 2684,73 2724,73 2774,73 2814,73 2854,73 2894,73 4166,72.92 4206,72.92 4246,72.92 4286,72.92 4336,72.92 4376,72.92 4416,72.92 4456,72.92 5728,72.84 5768,72.84 5808,72.84 5848,72.84 5898,72.84 5938,72.84 5978,72.84 6018,72.84 7290,72.76 7330,72.76 7370,72.76 7410,72.76 7460,72.76 7500,72.76 7540,72.76 7580,72.76 9245.7,72.69 9285.7,72.69 9325.7,72.69 9365.7,72.69 9415.7,72.69 9455.7,72.69 9495.7,72.69 9535.7,72.69 1129.33,112.56 1174.33,112.56 1219.33,112.56 1264.33,112.56 1309.33,112.56 1354.33,112.56 1399.33,112.56 1444.33,112.56 10807.7,112.61 10847.7,112.61 10887.7,112.61 10927.7,112.61 10977.7,112.61 11017.7,112.61 11057.7,112.61 11097.7,112.61 12369.7,112.53 12409.7,112.53 12449.7,112.53 12489.7,112.53 12539.7,112.53 12579.7,112.53 12619.7,112.53 12659.7,112.53 13931.7,112.45 13971.7,112.45 14011.7,112.45 14051.7,112.45 14101.7,112.45 14141.7,112.45 14181.7,112.45 14221.7,112.45 2604,113 2644,113 2684,113 2724,113 2774,113 2814,113 2854,113 2894,113 4166,112.92 4206,112.92 4246,112.92 4286,112.92 4336,112.92 4376,112.92 4416,112.92 4456,112.92 5728,112.84 5768,112.84 5808,112.84 5848,112.84 5898,112.84 5938,112.84 5978,112.84 6018,112.84 7290,112.76 7330,112.76 7370,112.76 7410,112.76 7460,112.76 7500,112.76 7540,112.76 7580,112.76 9245.7,112.69 9285.7,112.69 9325.7,112.69 9365.7,112.69 9415.7,112.69 9455.7,112.69 9495.7,112.69 9535.7,112.69 10807.7,152.61 10847.7,152.61 10887.7,152.61 10927.7,152.61 10977.7,152.61 11017.7,152.61 11057.7,152.61 11097.7,152.61 12369.7,152.53 12409.7,152.53 12449.7,152.53 12489.7,152.53 12539.7,152.53 12579.7,152.53 12619.7,152.53 12659.7,152.53 13931.7,152.45 13971.7,152.45 14011.7,152.45 14051.7,152.45 14101.7,152.45 14141.7,152.45 14181.7,152.45 14221.7,152.45 2604,153 2644,153 2684,153 2724,153 2774,153 2814,153 2854,153 2894,153 4166,152.92 4206,152.92 4246,152.92 4286,152.92 4336,152.92 4376,152.92 4416,152.92 4456,152.92 5728,152.84 5768,152.84 5808,152.84 5848,152.84 5898,152.84 5938,152.84 5978,152.84 6018,152.84 7290,152.76 7330,152.76 7370,152.76 7410,152.76 7460,152.76 7500,152.76 7540,152.76 7580,152.76 9245.7,152.69 9285.7,152.69 9325.7,152.69 9365.7,152.69 9415.7,152.69 9455.7,152.69 9495.7,152.69 9535.7,152.69 1129.33,157.56 1174.33,157.56 1399.33,157.56 1444.33,157.56 10807.7,192.61 10847.7,192.61 10887.7,192.61 10927.7,192.61 10977.7,192.61 11017.7,192.61 11057.7,192.61 11097.7,192.61 12369.7,192.53 12409.7,192.53 12449.7,192.53 12489.7,192.53 12539.7,192.53 12579.7,192.53 12619.7,192.53 12659.7,192.53 13931.7,192.45 13971.7,192.45 14011.7,192.45 14051.7,192.45 14101.7,192.45 14141.7,192.45 14181.7,192.45 14221.7,192.45 2604,193 2644,193 2684,193 2724,193 2774,193 2814,193 2854,193 2894,193 4166,192.92 4206,192.92 4246,192.92 4286,192.92 4336,192.92 4376,192.92 4416,192.92 4456,192.92 5728,192.84 5768,192.84 5808,192.84 5848,192.84 5898,192.84 5938,192.84 5978,192.84 6018,192.84 7290,192.76 7330,192.76 7370,192.76 7410,192.76 7460,192.76 7500,192.76 7540,192.76 7580,192.76 9245.7,192.69 9285.7,192.69 9325.7,192.69 9365.7,192.69 9415.7,192.69 9455.7,192.69 9495.7,192.69 9535.7,192.69 1129.33,202.56 1444.33,202.56 1129.33,522.56 1444.33,522.56 1129.33,567.56 1174.33,567.56 1399.33,567.56 1444.33,567.56 10807.7,602.61 11097.7,602.61 12369.7,602.53 12659.7,602.53 13931.7,602.45 14221.7,602.45 2604,603 2894,603 4166,602.92 4456,602.92 5728,602.84 6018,602.84 7290,602.76 7580,602.76 9245.7,602.69 9535.7,602.69 10807.7,642.61 11097.7,642.61 12369.7,642.53 12659.7,642.53 13931.7,642.45 14221.7,642.45 2604,643 2894,643 4166,642.92 4456,642.92 5728,642.84 6018,642.84 7290,642.76 7580,642.76 9245.7,642.69 9535.7,642.69 10807.7,682.61 10847.7,682.61 10887.7,682.61 11017.7,682.61 11057.7,682.61 11097.7,682.61 12369.7,682.53 12409.7,682.53 12449.7,682.53 12579.7,682.53 12619.7,682.53 12659.7,682.53 13931.7,682.45 13971.7,682.45 14011.7,682.45 14141.7,682.45 14181.7,682.45 14221.7,682.45 2604,683 2644,683 2684,683 2814,683 2854,683 2894,683 4166,682.92 4206,682.92 4246,682.92 4376,682.92 4416,682.92 4456,682.92 5728,682.84 5768,682.84 5808,682.84 5938,682.84 5978,682.84 6018,682.84 7290,682.76 7330,682.76 7370,682.76 7500,682.76 7540,682.76 7580,682.76 9245.7,682.69 9285.7,682.69 9325.7,682.69 9455.7,682.69 9495.7,682.69 9535.7,682.69
  other v4: 782.45,6730.33 821.82,6730.33 861.19,6730.33 900.56,6730.33 782.45,6769.7 821.82,6769.7 861.19,6769.7 900.56,6769.7 782.45,6809.07 821.82,6809.07 861.19,6809.07 900.56,6809.07
Protection_Ch1: R75_Ch1.1 R175_Ch1.1 U9_Ch1.2 U29_Ch1.14 | length 970.8
  Top Layer w15: U9_Ch1.2@1838.28,5748.55 1797.55,5748.55 1785,5736 1785,5661.2 R75_Ch1.1@1815.5,5630.7 1869.7,5630.7 1892.35,5653.35 R175_Ch1.1@1949.38,5653.35 v2(1949.38,5607.7)
  Bottom Layer w15: U29_Ch1.14@1731.61,5166.8 1731.61,5251.61 1762,5282 1889,5282 1949.38,5342.38 v2(1949.38,5607.7)
Protection_Ch2: R75_Ch2.1 R175_Ch2.1 U9_Ch2.2 U29_Ch2.14 | length 970.8
  Top Layer w15: U9_Ch2.2@3400.28,5748.47 3359.55,5748.47 3347,5735.92 3347,5661.12 R75_Ch2.1@3377.5,5630.62 3431.7,5630.62 3454.35,5653.28 R175_Ch2.1@3511.38,5653.28 v2(3511.38,5607.62)
  Bottom Layer w15: U29_Ch2.14@3293.61,5166.72 3293.61,5251.54 3324,5281.92 3451,5281.92 3511.38,5342.3 v2(3511.38,5607.62)
Protection_Ch3: R75_Ch3.1 R175_Ch3.1 U9_Ch3.2 U29_Ch3.14 | length 970.8
  Top Layer w15: U9_Ch3.2@4962.28,5748.39 4921.55,5748.39 4909,5735.84 4909,5661.04 R75_Ch3.1@4939.5,5630.54 4993.7,5630.54 5016.35,5653.2 R175_Ch3.1@5073.38,5653.2 v2(5073.38,5607.54)
  Bottom Layer w15: U29_Ch3.14@4855.61,5166.64 4855.61,5251.46 4886,5281.84 5013,5281.84 5073.38,5342.22 v2(5073.38,5607.54)
Protection_Ch4: R75_Ch4.1 R175_Ch4.1 U9_Ch4.2 U29_Ch4.14 | length 970.8
  Top Layer w15: U9_Ch4.2@6524.28,5748.31 6483.55,5748.31 6471,5735.76 6471,5660.96 R75_Ch4.1@6501.5,5630.46 6555.7,5630.46 6578.35,5653.12 R175_Ch4.1@6635.38,5653.12 v2(6635.38,5607.46)
  Bottom Layer w15: U29_Ch4.14@6417.61,5166.56 6417.61,5251.38 6448,5281.76 6575,5281.76 6635.38,5342.14 v2(6635.38,5607.46)
Protection_Ch5: R75_Ch5.1 R175_Ch5.1 U9_Ch5.2 U29_Ch5.14 | length 970.8
  Top Layer w15: U9_Ch5.2@8479.98,5748.24 8439.25,5748.24 8426.7,5735.69 8426.7,5660.88 R75_Ch5.1@8457.2,5630.39 8511.4,5630.39 8534.06,5653.04 R175_Ch5.1@8591.08,5653.04 v2(8591.08,5607.39)
  Bottom Layer w15: U29_Ch5.14@8373.32,5166.48 8373.32,5251.3 8403.7,5281.69 8530.7,5281.69 8591.08,5342.06 v2(8591.08,5607.39)
Protection_Ch6: R75_Ch6.1 R175_Ch6.1 U9_Ch6.2 U29_Ch6.14 | length 970.8
  Top Layer w15: U9_Ch6.2@10041.98,5748.16 10001.25,5748.16 9988.7,5735.61 9988.7,5660.8 R75_Ch6.1@10019.2,5630.31 10073.4,5630.31 10096.06,5652.96 R175_Ch6.1@10153.08,5652.96 v2(10153.08,5607.31)
  Bottom Layer w15: U29_Ch6.14@9935.32,5166.4 9935.32,5251.22 9965.7,5281.61 10092.7,5281.61 10153.08,5341.98 v2(10153.08,5607.31)
Protection_Ch7: R75_Ch7.1 R175_Ch7.1 U9_Ch7.2 U29_Ch7.14 | length 970.8
  Top Layer w15: U9_Ch7.2@11603.98,5748.08 11563.25,5748.08 11550.7,5735.53 11550.7,5660.72 R75_Ch7.1@11581.2,5630.23 11635.4,5630.23 11658.06,5652.88 R175_Ch7.1@11715.08,5652.88 v2(11715.08,5607.23)
  Bottom Layer w15: U29_Ch7.14@11497.32,5166.32 11497.32,5251.14 11527.7,5281.53 11654.7,5281.53 11715.08,5341.91 v2(11715.08,5607.23)
Protection_Ch8: R75_Ch8.1 R175_Ch8.1 U9_Ch8.2 U29_Ch8.14 | length 970.8
  Top Layer w15: U9_Ch8.2@13165.98,5748 13125.25,5748 13112.7,5735.45 13112.7,5660.65 R75_Ch8.1@13143.2,5630.15 13197.4,5630.15 13220.06,5652.8 R175_Ch8.1@13277.08,5652.8 v2(13277.08,5607.15)
  Bottom Layer w15: U29_Ch8.14@13059.32,5166.24 13059.32,5251.06 13089.7,5281.45 13216.7,5281.45 13277.08,5341.83 v2(13277.08,5607.15)
RESET1: C72.2 C93.2 R109.1 R114.2 R140.1 R145.2 R282.1 S1.1 S2.1 TP17.1 TP23.1 U28.1 | length 9573.5
  Top Layer w10: R114.2@4556.74,7435.01 4593.53,7471.8 4593.53,7545.63 4639.91,7592.01 R109.1@4643.62,7592.01 C72.2@4643.62,7656.01 4643.62,7764.21 S1.1@4644.42,7765.01 4644.42,7823.32 TP17.1@4722.11,7901.01 ; v2(6931,8053) 6949.28,8034.72 R282.1@6949.28,7903.32 ; v2(7153,6934) 7170.51,6951.51 U28.1@7218,6951.51 ; R145.2@11198.44,7434.7 11235.23,7471.49 11235.23,7545.32 11281.61,7591.7 R140.1@11285.32,7591.7 C93.2@11285.32,7655.7 11285.32,7763.89 S2.1@11286.12,7764.7 11286.12,7823 TP23.1@11363.82,7900.7
  Signal Layer 2 w10: v2(6931,8053) 7003,8053 7227.5,7828.5 7227.5,7008.5 v2(7153,6934)
  Bottom Layer w10: TP17.1@4722.11,7901.01 4874.1,8053 v2(6931,8053) 6963,8053 7126,7890 10466,7890 10693,8117 11147.51,8117 TP23.1@11363.82,7900.7
SCLK1: R106.2 R298.1 TP14.1 | length 3750.8
  Top Layer w10: TP14.1@4443.11,7901.01 4495.99,7848.14 4495.99,7676.09 4469.11,7649.22 R106.2@4469.11,7584.63 ; R298.1@7439,7316.38 v2(7479.7,7316.38)
  Bottom Layer w10: TP14.1@4443.11,7901.01 4443.11,7823.88 4602,7665 5184,7665 5577,7272 7435.32,7272 v2(7479.7,7316.38)
SCLK2: R137.2 R288.1 TP20.1 | length 4653.5
  Top Layer w10: R288.1@7133,7316.38 7133,7239 v2(7134,7238) ; TP20.1@11084.82,7900.7 11137.69,7847.82 11137.69,7675.78 11110.82,7648.91 R137.2@11110.82,7584.32
  Bottom Layer w10: v2(7134,7238) 7978,7238 8346.7,7606.7 9877.7,7606.7 9949,7678 10862.12,7678 TP20.1@11084.82,7900.7
SW_Ch1: C1_Ch1.2 C2_Ch1.1 D2_Ch1.4 L2_Ch1.1 Q1_Ch1.1 Q1_Ch1.2 Q1_Ch1.3 Q7_Ch1.5 Q7_Ch1.6 Q7_Ch1.7 Q7_Ch1.8 Q7_Ch1.9@2572,3385.47 R9_Ch1.1 R18_Ch1.1 TP2_Ch1.1 U1_Ch1.6 | length 1490.1
  Top Layer w15: TP2_Ch1.1@1745.39,3199.31 1830.16,3284.07 1830.16,3323.07 ; R18_Ch1.1@1897.37,3323.07 1830.16,3323.07 ; C1_Ch1.2@1962.33,3601.87 1960.08,3604.11 1813.11,3604.11 1798.37,3589.37 U1_Ch1.6@1798.37,3545.79 1798.37,3354.86 1830.16,3323.07
  Signal Layer 2 w15: TP2_Ch1.1@1745.39,3199.31 1759.7,3185 2251,3185 2390,3324 2437,3371 v1(2476,3371)
  other v1: 2476,2904 2546,2904 2616,2904 2686,2904 2476,2974 2546,2974 2616,2974 2686,2974 2476,3044 2546,3044 2616,3044 2686,3044 2476,3114 2546,3114 2616,3114 2686,3114 2476,3184 2546,3184 2616,3184 2686,3184 2476,3254 2546,3254 2616,3254 2686,3254 2686,3324 2686,3394 2686,3464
